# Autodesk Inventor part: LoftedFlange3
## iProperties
Created: 2008-12
Part Number: LoftedFlange3
Material: Default
Document SubType Name: Sheet Metal
Designer: Designer
Density: 1 g/cm^3
Sheet Metal Rule: Default_mm
Author: Designer
